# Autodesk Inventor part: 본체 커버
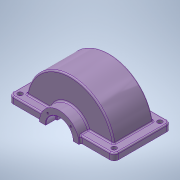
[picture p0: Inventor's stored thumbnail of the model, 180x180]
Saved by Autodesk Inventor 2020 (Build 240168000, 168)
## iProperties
Created: 2023-06
Part Number: 본체 커버
Material: 알루미늄 6061
Document SubType Name: Modeling
Designer: mdu-01
Density: 2.71 g/cm^3
Appearance: 알루미늄 - 평지(1)
Mass: 2296.01 g
Surface Area: 1364.02 cm^2
Volume: 847.238 cm^3
Author: mdu-01
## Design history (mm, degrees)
sketch "스케치1"
  geometry: L1 (0, 70)-(0, -70); L2 (0, 70)-(45, 70); L3 (45, 70)-(45, 45); L4 (45, 45)-(100, 45); L5 (0, 0)-(100, 0); L6 (0, -70)-(45, -70); L7 (45, -70)-(45, -45); L8 (45, -45)-(100, -45); L9 (100, 45)-(100, -45); 1 further point
  constraints: 18 end point, 3 perpendicular, 3 symmetric about line, 2 midpoint, 2 parallel, 1 coincident, 1 vertical
  dimensions: "d0" = 140 distance of L1.start L1.end; "d1" = 90 diameter of L3 L1; "d2" = 90 distance between parallel lines of L8 L4; "d3" = 200 diameter of L9 L1
revolve "회전1" sketch "스케치1" stored, may be unused: angle "d4" = 180 deg
sketch "스케치2"
  geometry: L1 (-10, -110)-(210, -110); L2 (220, -100)-(220, 10); L3 (210, 20)-(-10, 20); L4 (-20, 10)-(-20, -100); L5 (-20, -110)-(220, 20); L6 (220, -110)-(-20, 20); A1 r 10 centre (-10, 10) between (-10, 20) and (-20, 10); A2 r 10 centre (210, 10) between (220, 10) and (210, 20); A3 r 10 centre (210, -100) between (210, -110) and (220, -100); A4 r 10 centre (-10, -100) between (-20, -100) and (-10, -110); 1 further point
  constraints: 12 end point, 8 point on circle, 8 point on line, 8 tangent, 4 centre point, 3 equal radius, 2 midpoint, 2 parallel, 1 horizontal, 1 perpendicular
  dimensions: "d5" = 240 distance of L6.end L5.end; "d6" = 130 distance of L5.end L6.start; "d7" = 10 radius of A1
extrude "돌출1" join sketch "스케치2" distance "d8" = 15; taper "d9" = 0 deg
sketch "스케치3"
  geometry: L1 (0, 70)-(45, 70) reference; L2 (0, -70)-(45, -70) reference; L3 (0, 70)-(0, -70); L4 (31, 70)-(31, 48); L5 (30, 47)-(27.5, 47); L6 (27.5, 47)-(27.5, 32); L7 (27.5, 32)-(87, 32); L8 (0, 0)-(92.097, 0); L9 (31, -70)-(31, -48); L10 (30, -47)-(27.5, -47); L11 (27.5, -47)-(27.5, -32); L12 (27.5, -32)-(87, -32); L13 (87, 32)-(87, -32); L14 (0, 70)-(31, 70); L15 (0, -70)-(31, -70); A1 r 1 centre (30, 48) between (30, 47) and (31, 48); A2 r 1 centre (30, -48) between (31, -48) and (30, -47); 2 further points
  constraints: 26 end point, 5 point on line, 5 symmetric about line, 4 parallel, 4 point on circle, 4 tangent, 3 perpendicular, 2 centre point, 2 collinear, 1 equal radius
  dimensions: "d10" = 1 radius of A1; "d11" = 62 diameter of L4 L3; "d12" = 23 distance between parallel lines of L1 L5; "d13" = 64 distance between parallel lines of L12 L7; "d14" = 55 diameter of L6 L3; "d15" = 87 distance between parallel lines of L13 L3
revolve "회전2" sketch "스케치3" stored, may be unused: angle "d16" = 180 deg
fillet "모깎기1" dims "d17" = 3
fillet "모깎기2" dims "d18" = 3
sketch "스케치4"
  geometry: L1 (-7, -7)-(207, -7); L2 (207, -7)-(207, 97); L3 (207, 97)-(-7, 97); L4 (-7, 97)-(-7, -7); L5 (-7, -7)-(207, 97); L6 (207, -7)-(-7, 97); 1 further point
  constraints: 12 end point, 2 midpoint, 2 parallel, 1 horizontal, 1 perpendicular
  dimensions: "d19" = 214 distance of L3.end L2.end; "d20" = 104 distance of L2.end L1.end
hole "구멍1" sketch "스케치4" at (207, -7), (-7, -7), (207, 97), (-7, 97) diameter "d21" = 6.6; stored, may be unused: countersink angle "d25" = 90 deg, drill point angle "d27" = 118 deg; dims "d22" = 6, "d23" = 11, "d24" = 6.8, "d26" = 8
sketch "스케치5"
  geometry: L1 (-26.163, 26.163)-(26.163, 26.163); L2 (26.163, 26.163)-(26.163, -26.163); L3 (26.163, -26.163)-(-26.163, -26.163); L4 (-26.163, -26.163)-(-26.163, 26.163); A1 r 37 centre (0, 0) between (-26.163, 26.163) and (26.163, -26.163); 1 further point
  constraints: 8 end point, 3 point on circle, 2 parallel, 2 perpendicular, 1 centre point, 1 coincident, 1 horizontal
  dimensions: "d28" = 74 diameter of A1
hole "구멍2" sketch "스케치5" at (-26.163, 26.163), (26.163, 26.163) diameter "d29" = 4.134; stored, may be unused: countersink angle "d33" = 90 deg, drill point angle "d35" = 118 deg; dims "d30" = 10, "d31" = 11, "d32" = 6.8, "d34" = 12
chamfer "모따기1" distance "d36" = 1; stored, may be unused: second distance "d37" = 2, angle "d38" = 45 deg
node "솔리드1"
mirror "대칭1"
